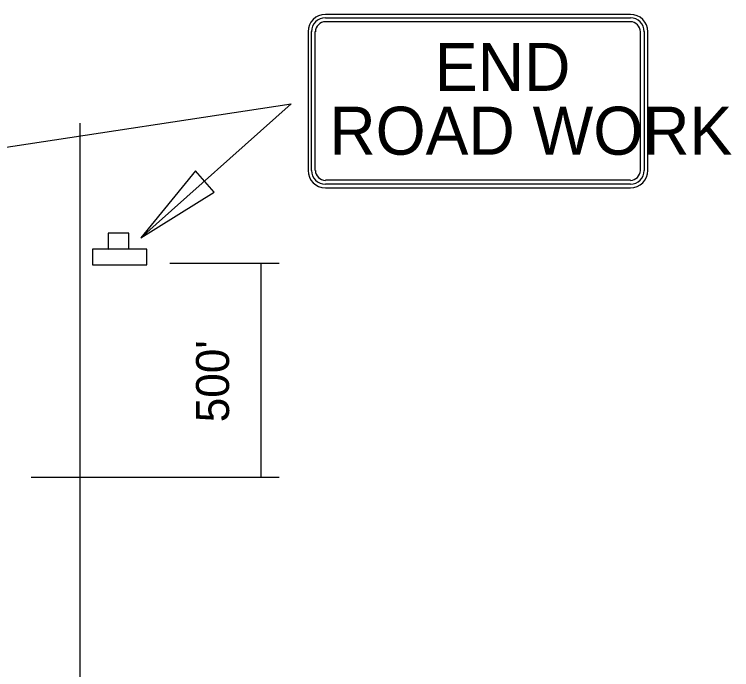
# Model space of a CAD drawing. Extents: x 1531.88 to 1538.58, y 1529.59 to 1539.31.
# Drawn here: x 1537.131 to 1538.436, y 1538.033 to 1539.224 of the extents above; entities that cross this region are included whole.
import ezdxf

# ---------------------------------------------------------------- set-up
doc = ezdxf.new("R2010")
doc.units = 0
for name, color, linetype in [('DETL-DIMS', 7, 'Continuous'), ('DETL-LINE', 7, 'Continuous'), ('DETL-NOTE', 7, 'Continuous'), ('USER-BORD', 7, 'Continuous')]:
    doc.layers.add(name, color=color, linetype=linetype)

# ---------------------------------------------------------------- blocks, each defined once
blk = doc.blocks.new('SIGN13')
at = {"layer": 'USER-BORD'}
for points in [[(-0.0134, 0.0182), (0.011, 0.0189), (0.011, 0.0371), (-0.0134, 0.0371)], [(-0.0314, 0.0182), (-0.0314, 0), (0.032, 0), (0.032, 0.0182)]]:
    blk.add_lwpolyline(points, close=True, dxfattribs=at)

msp = doc.modelspace()

# ---------------------------------------------------------------- linework, layer by layer
at = {"layer": 'DETL-DIMS'}
for p, q in [((1535.9884, 1538.8126), (1537.6347, 1539.0613)), ((1537.6347, 1539.0613), (1537.3615, 1538.8181)), ((1537.4139, 1538.7722), (1537.6131, 1538.7722)), ((1537.5797, 1538.7722), (1537.5797, 1538.3828)), ((1537.1619, 1538.3828), (1537.6131, 1538.3828))]:
    msp.add_line(p, q, dxfattribs=at)
msp.add_lwpolyline([(1537.4948, 1538.9012), (1537.4606, 1538.94), (1537.3615, 1538.8181)], close=True, dxfattribs=at)
at = {"layer": 'DETL-LINE'}
for p, q in [((1538.2516, 1539.2242), (1537.6969, 1539.2242)), ((1537.6969, 1539.2178), (1538.2516, 1539.2178)), ((1537.6969, 1539.2111), (1538.2516, 1539.2111)), ((1537.6655, 1539.1929), (1537.6655, 1538.9406)), ((1537.6719, 1538.9406), (1537.6719, 1539.1929)), ((1537.6786, 1538.9406), (1537.6786, 1539.1929)), ((1538.2696, 1539.1929), (1538.2696, 1538.9406)), ((1538.2697, 1539.1927), (1538.2696, 1539.1929)), ((1538.2769, 1539.1929), (1538.2769, 1538.9406)), ((1538.2833, 1538.9406), (1538.2833, 1539.1929)), ((1537.2503, 1539.0264), (1537.2503, 1532.2422)), ((1538.2516, 1538.9226), (1537.6969, 1538.9226)), ((1538.2516, 1538.9154), (1537.6969, 1538.9154)), ((1537.6969, 1538.909), (1538.2516, 1538.909))]:
    msp.add_line(p, q, dxfattribs=at)
for centre, radius, start, end in [((1537.697, 1539.1927), 0.0316, 90, 180), ((1538.2516, 1539.1927), 0.0316, 0, 90), ((1537.697, 1539.1927), 0.0252, 90, 180), ((1537.697, 1539.1927), 0.0181, 90, 180), ((1538.2516, 1539.1927), 0.0252, 0, 90), ((1538.2516, 1539.1927), 0.0181, 0, 90), ((1537.697, 1538.9406), 0.0316, 180, 270), ((1537.697, 1538.9406), 0.0252, 180, 270), ((1537.697, 1538.9406), 0.0181, 180, 270), ((1538.2516, 1538.9406), 0.0316, 270, 0), ((1538.2516, 1538.9406), 0.0181, 270, 0), ((1538.2516, 1538.9406), 0.0252, 270, 0)]:
    msp.add_arc(centre, radius, start, end, dxfattribs=at)

# ---------------------------------------------------------------- block references
at = {"layer": 'DETL-LINE', "xscale": 1.554867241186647, "yscale": 1.5548672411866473}
msp.add_blockref('SIGN13', (1537.3225, 1538.7689), dxfattribs=at)

# ---------------------------------------------------------------- texts
at = {"layer": 'DETL-LINE'}
for s, p in [('END', (1537.8961, 1539.0851)), ('ROAD WORK', (1537.7041, 1538.9691))]:
    msp.add_text(s, height=0.08731, rotation=360, dxfattribs=at).set_placement(p)
at = {"layer": 'DETL-NOTE'}
msp.add_text("500'", height=0.06, rotation=90, dxfattribs=at).set_placement((1537.5218, 1538.4826))

doc.saveas('drawing.dxf')
